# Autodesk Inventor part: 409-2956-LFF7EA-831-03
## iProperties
Created: 2010-09
Part Number: 409-2956-LFF7EA-831-03
Material: 3/8" OD TUBE - SS
Document SubType Name: Modeling
Designer: S. Boerckel
Engineer: Steve Boerckel
Mass: 61.6007 g
Surface Area: 127.01 cm^2
Volume: 7.62385 cm^3
Density: 8.08 g/cm^3
Description: LOWE PRESSURE GAUGE TUBE
LGTH: 2.820 in
Author: S. Boerckel
Revision Number: 0
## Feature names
1. Sweep3
